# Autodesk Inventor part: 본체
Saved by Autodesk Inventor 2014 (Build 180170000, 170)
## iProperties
Created: 2026-09
Part Number: 본체
Material: 알루미늄 6061
Document SubType Name: Modeling
Designer: dg
Density: 2.71 g/cm^3
Appearance: 알루미늄 - 평지
Author: jhkim
Creation Date: 2026-08-26
Sending System: Autodesk Inventor 2027
Preprocessor: ST-DEVELOPER v20.1
Author: dg
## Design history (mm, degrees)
node "본체1"
node "솔리드1"
node "기준1"
